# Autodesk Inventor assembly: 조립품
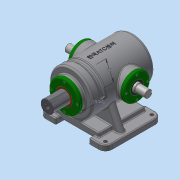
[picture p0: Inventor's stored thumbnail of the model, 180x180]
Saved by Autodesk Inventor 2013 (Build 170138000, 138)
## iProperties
Created: 2018-06
Part Number: 조립품
Document SubType Name: Assembly
Designer: Administrator
Mass: 8560.47 g
Surface Area: 4294.68 cm^2
Volume: 2307.06 cm^3
Density: 3.71055 g/cm^3
Author: Administrator
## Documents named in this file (13)
- C:\Users\Administrator\Desktop\380628V1001\조립품.iam
- C:\Users\Administrator\Desktop\380628V1001\본체.ipt
- C:\Users\Administrator\Desktop\380628V1001\가변스프링.ipt
- C:\Users\Administrator\Desktop\380628V1001\베어링 6205.ipt
- 베어링 6205.ipt
- C:\Users\Administrator\Desktop\380628V1001\볼트 M4.ipt
- C:\Users\Administrator\Desktop\380628V1001\부시.ipt
- C:\Users\Administrator\Desktop\380628V1001\슬라이드 커버.ipt
- C:\Users\Administrator\Desktop\380628V1001\슬라이드.ipt
- C:\Users\Administrator\Desktop\380628V1001\오일실.ipt
- 오일실.ipt
- C:\Users\Administrator\Desktop\380628V1001\축 커버.ipt
- C:\Users\Administrator\Desktop\380628V1001\편심축.ipt
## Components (1 placed, 1 different names)
1. 가변스프링:1
